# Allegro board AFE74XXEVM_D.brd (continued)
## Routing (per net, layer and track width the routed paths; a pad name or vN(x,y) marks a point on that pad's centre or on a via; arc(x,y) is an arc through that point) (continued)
N19409548: length 12.5
  TOP w0.127: U7.20 175.62,111.64 175.62,112.62 178.08,115.09 181.81,115.09 182.04,115.32 183.82,115.32 184.31,114.82 U5.26
N19409557: length 8.9
  TOP w0.127: v1(177.42,112.19) 177.42,111.47 177.19,111.24 177.19,111.09 176.82,110.72 U7.18
  BOTTOM w0.127: v3(183.81,113.37) 183.81,113.35 182.78,112.32 177.55,112.32 v1(177.42,112.19)
N19409566: length 9.4
  L4_SIG w0.127: v3(176.53,110.22) 177.94,110.22 178.08,110.08 182.14,110.08 182.83,110.77 182.83,112.89 v3(183.31,113.37)
N19409575: length 8.8
  L4_SIG w0.127: v3(176.53,109.72) 176.21,110.04 176.21,110.06 176.19,110.08 176.19,110.37 176.54,110.72 178.1,110.72 178.43,111.05 179.65,111.05 180.86,112.26 181.88,112.26 182.37,112.75 182.37,112.98 182.76,113.37 v3(182.81,113.37)
N19410556: length 11.7
  TOP w0.127: U5.30 v1(182.31,114.88)
  BOTTOM w0.127: v3(176.53,109.22) 176.56,109.22 177.24,109.91 177.24,111.66 176.83,112.06 176.83,112.5 179.22,114.88 v1(182.31,114.88)
N19410565: length 7.8
  TOP w0.127: U5.32 181.28,113.41 179.81,113.41 177.47,111.07 177.47,110.16 177.17,109.86 177.17,108.92 176.97,108.72 U7.14
N19410574: length 5.4
  TOP w0.127: U7.13 176.98,108.22 177.47,108.71 177.47,109.58 177.83,109.93 177.83,111.02 178.3,111.5 U5.33
N19410583: length 5.5
  TOP w0.127: U7.12 177.04,107.72 177.83,108.51 177.83,109.3 178.13,109.6 178.13,110.85 178.28,111 U5.34
N19439857: length 1.6
  BOTTOM w0.127: R33.1 151.05,114.6 J12.1
N19439882: length 1.6
  BOTTOM w0.127: J12.3 153.54,114.55 R32.1
N19439919: length 1.6
  BOTTOM w0.127: R35.1 156.11,114.58 J12.5
N19439930: length 1.6
  BOTTOM w0.127: R34.1 158.72,114.66 J12.7
N19439963: length 1.5
  BOTTOM w0.127: R36.1 161.42,114.81 J12.9
N19439974: length 1.6
  BOTTOM w0.127: J12.11 163.7,114.55 R37.1
N19440007: length 1.6
  BOTTOM w0.127: J12.13 166.24,114.55 R39.1
N19440018: length 1.6
  BOTTOM w0.127: J12.15 168.78,114.55 R38.1
N19452593:
  vias: v1(117.88,96.55)
N19452616: length 5.7
  TOP w0.127: R18.1 117.75,95.53 116.84,96.44 116.84,98.96 D1.2
N19452717:
  vias: v1(120.27,96.52)
N19452732: length 12.3
  TOP w0.127: D2.2 117.45,102.54 117.45,97.59 117.98,97.05 118.72,97.05 120.24,95.53 R19.1
N19463241:
  vias: v1(119.35,11.39)
N19466012: length 1.8
  TOP w0.305: U29.14 134.53,24.32 R279.1
N19467594: length 0.3
  BOTTOM w0.254: v1(61.55,62.3) 61.73,62.49 R20.1
N19500229: length 43.9
  BOTTOM w0.127: R26.2 123.6,93.7 Q3.3 Q4.3 Q5.3 Q6.3 Q7.3 Q8.3 Q9.3 Q10.3 Q11.3 Q12.3 Q13.3 Q14.3 Q15.3 Q16.3 Q17.3 Q18.3 Q19.3 Q20.3
N19509945: length 7.6
  TOP w0.127: D3.2 117.14,93.73 v1(122.56,93.73)
N19512252: length 6
  BOTTOM w0.127: v3(176.61,101.74) 177.56,101.74 179.07,103.25 179.07,105.65 179.42,106 v3(179.44,106)
N19512261: length 6.3
  BOTTOM w0.127: v3(176.61,101.24) 177.59,101.24 179.81,103.46 179.81,105.15 179.46,105.5 v3(179.44,105.5)
N19512270: length 6.8
  TOP w0.127: U9.12 177.22,100.74 177.72,101.24 177.72,104.62 178.1,105 U5.46
N19520191: length 11.8
  TOP w0.127: U5.55 184.31,97.17 183.26,96.11 181.79,96.11 180.23,94.55 U10.10
N19520200: length 11.8
  TOP w0.127: U5.57 185.31,99.85 184.68,99.22 184.68,96.93 183.49,95.73 182.14,95.73 180.88,94.47 U10.11
N19525330: length 11.8
  TOP w0.127: U5.59 186.31,100.78 186.09,100.55 186.09,99.33 185.88,99.11 185.88,96.85 183.97,94.95 182.5,94.95 182.18,94.63 U10.13
N19525339: length 11.8
  TOP w0.127: U10.12 181.53,94.51 182.35,95.33 183.69,95.33 185.04,96.67 185.04,97.71 185.03,97.72 185.03,98.07 185.04,98.08 185.04,99.01 185.81,99.78 U5.58
N19667706: length 2.2
  TOP w0.127: D14.1 211.96,89.81 R287.2
N19816997: length 2
  BOTTOM w0.381: C2.2 43.84,69.32 arc(43.67,69.2) 43.47,69.16 T1.4
N19898860: length 15.9
  TOP w0.127: J36.3 161.37,91.9 163.17,93.7 170.74,93.7 172.16,95.12 173.16,95.12 173.7,95.66 U33.13
N19898869: length 13.9
  TOP w0.127: J36.6 165.33,92.76 170.51,92.76 171.88,94.13 173.2,94.13 174.35,95.28 U33.12
N19898878: length 12
  TOP w0.127: U33.11 175,95.32 173.48,93.8 172.24,93.8 170.73,92.29 167.4,92.29 J36.9
N19898887: length 10.2
  TOP w0.127: J36.12 170.46,91.34 172.57,93.45 173.91,93.45 175.65,95.18 U33.10
N20069404: length 13.3
  TOP w0.305: v1(92.04,18.71) 91.61,18.71 91.42,18.53 Q25.D2
  L6_SIG w0.127: v3(91.3,8.44) 91.3,9.44 90.14,10.59 90.14,11.89 v1(89.18,12.85)
  BOTTOM w0.127: v1(89.18,12.85) 89.18,15.37 92.04,18.23 v1(92.04,18.71)
N20069410: length 14.9
  TOP w0.305: L45.1 95.43,8.31 93.92,8.95 93.66,8.95 95.35,8.97 L45.1 ; L45.1 97,9.19 95.25,9.19 93.85,8.99 ; L45.1 97,8.33 93.85,8.99 ; 93.85,8.99 U13.7
N20069434: length 2.2
  TOP w0.305: R233.2 R228.1 93.1,6.67 U13.5
N20069690: length 1.7
  TOP w0.305: 90.18,17.7 Q25.6 90.93,17.41 Q25.D1 ; 90.18,17.7 v1(90.17,17.7) ; 90.18,17.7 Q25.5
N20069712: length 2.1
  BOTTOM w0.305: R229.1 R232.1 v1(79.76,14.5)
N20069759:
  vias: v1(81.41,14.5)
N20070471: length 1.7
  TOP w0.305: 167.82,32.51 167.72,32.61 U32.1
  TOP w0.381: v1(170.18,31.8) 169.96,31.58 U32.20
  vias: v1(170.18,32.72) v1(171.15,32.72) v1(171.15,31.8) v1(172.11,32.74) v1(172.11,31.83)
N20070473:
  vias: v1(167.03,27.51)
N20070515: length 0.3
  BOTTOM w0.381: R298.2 165.74,27.71 v1(165.77,27.67)
N20070523: length 0.4
  TOP w0.381: U32.11 164.88,27.91 v1(164.8,27.91)
N20070610:
  vias: v1(163.81,28.98)
N20070750: length 0.1
  BOTTOM w0.381: v1(163.81,29.63) 163.8,29.64 R300.2
N20073169: length 14
  TOP w0.381: v3(165.71,13.96) v3(165.71,14.48) 165.71,15.54 ; 165.71,15.54 165.91,17.45 166.04,19 v1(165.58,19) L48.1 ; 165.71,15.54 165.71,16.23 ; 165.71,15.54 165.74,15.75 165.61,16.76 165.56,17.53 165.55,18.36 ; 165.71,16.23 165.55,18.36 ; 165.71,16.23 165.71,18.2 165.55,18.36
  vias: v1(165.63,18.34) v1(165.61,17.73) v3(165.71,13.46)
N20073179: length 14
  TOP w0.381: v1(165.77,8.05) 165.71,8.12 165.63,8.81 165.71,11.13 ; v1(165.77,8.05) 165.63,9.12 165.61,7.39 165.68,7.42 166.14,7.39 165.75,10.63 ; v1(165.77,8.05) 165.89,9.04 165.81,9.27 165.75,10.63 ; 165.71,11.13 v3(165.71,11.84) v3(165.71,12.36) ; 165.71,11.13 165.75,10.63
  vias: v1(165.79,8.71) v1(165.81,7.42) v3(165.71,12.88)
N20073199: length 2.7
  TOP w0.254: R247.2 v1(163.16,12.78)
  TOP w0.305: U18.14 163.96,13.16 163.59,12.78 R247.2 162.24,13.73 R248.1
N20073285:
  vias: v1(167.11,12.11)
N20073325:
  vias: v1(164.31,14.2)
N20074418:
  vias: v1(145.57,26.47)
N20074438: length 2.2
  TOP w0.203: 143.66,32.84 C406.1 143.66,30.77 C407.1
  vias: v1(143.71,29.97) v1(143.76,32.51) v1(143.76,31.09) v1(145.03,32.56) v1(145.01,31.37) v1(145.01,30.1) v1(145.92,32.56) v1(145.9,31.37) v1(145.9,30.12) v1(146.79,32.56) v1(146.76,31.37) v1(146.79,30.1)
N20074448: length 1.3
  TOP w0.381: v1(150.24,27.13) 150.26,27.11 U27.12 151.01,27.11 v1(151.03,27.13)
  BOTTOM w0.305: C412.1 v1(150.24,27.13)
N20074452: length 0.3
  BOTTOM w0.305: R276.2 146.58,25.23 v1(146.66,25.16)
N20074454: length 1.7
  TOP w0.305: U27.3 143.87,27.76 C408.1
N20074458: length 0.2
  BOTTOM w0.305: R278.2 147.42,25.27 v1(147.31,25.16)
N20074494: length 2.5
  TOP w0.254: R275.1 148.39,32.12 148.38,32.12 148.25,32.25 148.25,32.26 147.84,32.66 R274.1
  TOP w0.305: R274.1 147.73,33.6 PP25.1
N20074551: length 0.6
  BOTTOM w0.305: U28.1 148.7,32.66 v1(148.73,32.69)
N20074589: length 2
  TOP w0.305: C409.1 152.48,27.76 U27.13
N20074804: length 1.3
  TOP w0.381: v1(150.24,28.42) 150.25,28.41 U27.14 150.87,28.41 v1(150.88,28.42)
  BOTTOM w0.305: v1(150.88,28.42) R273.1 v1(150.24,28.42)
N20081535: length 0.4
  TOP w0.305: v1(80.98,22.91) 80.78,22.72 U22.6
N20081541: length 1.9
  TOP w0.305: C373.1 86.17,25.7 C452.1
  vias: v1(84.69,23.94) v1(85.32,25.55) v1(86,22.64) v1(86,21.99) v1(86.69,25.55) v1(87.86,25.58) v1(88.13,22.54) v1(88.16,23.34)
N20081551:
  vias: v1(82.73,19.08) v1(82.73,18.41)
N20081555:
  vias: v1(80.98,22)
N20081559: length 1.8
  TOP w0.305: C377.1 83.39,25.45 U22.3
N20081574:
  vias: v1(80.78,20.04)
N20081656: length 2.5
  TOP w0.305: R256.1 87.68,20.65 88.6,21.56 R255.1 PP16.1
N20081707: length 0.5
  BOTTOM w0.305: U21.1 88.55,20.64 v1(88.6,20.6)
N20081783: length 1.7
  TOP w0.305: C381.1 83.39,17.02 U22.13
N20082233:
  vias: v1(84.04,18.73)
N20086063: length 0.3
  BOTTOM w0.381: R270.2 126.67,5.21 v1(126.82,5.06)
N20086075: length 1.9
  TOP w0.305: v1(123.93,12.29) 123.8,12.17 C397.1 123.8,10.67 v1(123.98,10.49)
  vias: v1(123.95,11.4) v1(123.98,9.55) v1(126.01,12.52) v1(125.98,11.35) v1(125.96,10.29) v1(127.03,11.35) v1(127,10.29) v1(127.05,12.52)
N20086085: length 0.4
  BOTTOM w0.381: C401.1 130.74,7.04 v1(130.72,7.02)
N20086089: length 0.2
  BOTTOM w0.381: v1(127.47,5.06) 127.58,5.18 R271.2
N20086091: length 1.8
  TOP w0.305: U25.3 124,7.67 C399.1
N20086095:
  vias: v1(129.44,5.18)
N20086131: length 2.8
  TOP w0.254: R269.1 128.91,11.81 R268.1
  TOP w0.305: R268.1 127.97,13.92 PP23.1
N20086161: length 0.6
  BOTTOM w0.305: U26.1 128.92,12.68 v1(128.98,12.75)
N20086199: length 1.9
  TOP w0.305: U25.13 C400.1
N20086237:
  vias: v1(130.72,8.32)
N20090664: length 0.2
  BOTTOM w0.381: R261.1 121.74,24.36 v1(121.68,24.42)
N20090676: length 2.4
  TOP w0.203: 114.91,28.7 114.78,28.57 C386.1 114.78,26.6 C453.1
  vias: v1(114.94,28.5) v1(114.94,27.64) v1(114.94,26.64) v1(114.91,25.73) v1(116.41,28.65) v1(116.38,27.69) v1(116.41,26.72) v1(117.32,28.65) v1(117.37,27.71) v1(117.35,26.75) v1(118.19,28.65) v1(118.21,27.69) v1(118.21,26.75)
N20090711: length 0.3
  BOTTOM w0.381: v1(116.47,22.47) 116.57,22.38 R263.2
N20090727: length 0.4
  BOTTOM w0.381: C391.1 121.85,22.96 v1(121.68,23.12)
N20090731:
  vias: v1(117.78,21.17)
N20090737: length 1.8
  TOP w0.305: U23.3 114.88,23.77 C390.1
N20090741:
  vias: v1(119.76,21.08)
N20090777: length 2.7
  TOP w0.254: R262.1 120.03,27.74 R264.1
  TOP w0.305: R262.1 119.09,29.8 PP21.1
N20090807: length 0.5
  BOTTOM w0.305: v1(120.05,28.71) 120.08,28.68 U24.1
N20090845: length 1.8
  TOP w0.305: C392.1 123.44,23.77 U23.13
N20133985: length 3
  TOP w0.381: 43.34,33.08 43.58,33.97 arc(43.64,34.1) 43.76,34.2 44.21,34.46 arc(44.36,34.59) 44.45,34.78 T5.1
N20133989: length 3
  TOP w0.381: T5.3 41.98,35.37 arc(41.97,35.22) 42.02,35.07 42.31,34.57 arc(42.36,34.43) 42.35,34.28 T4.4
N20135778:
  vias: v1(43.62,36.54)
N20136307: length 3.2
  TOP w0.381: C141.1 59.25,39.84 arc(58.97,39.01) 59.03,38.14 T9.4
N20136325: length 1.8
  TOP w0.381: C141.2 59.06,40.97 L9.2 58.91,41.52 58.74,42.12 C142.2
N20136327: length 1.8
  TOP w0.381: C143.2 59.72,42.39 L9.1 60.05,41.15 C140.2
N20136329: length 1.8
  TOP w0.381: C143.1 59.49,43.34 L10.1 59.17,44.56 R77.2
N20136331: length 1.8
  TOP w0.381: C142.1 58.52,43.04 L10.2 58.19,44.2 R73.2
N20136361: length 3
  TOP w0.381: T9.1 62.8,33.87 arc(62.81,33.72) 62.76,33.58 62.47,33.07 arc(62.43,32.93) 62.44,32.79 T8.5
N20136363: length 3
  TOP w0.381: T8.4 61.21,32.44 arc(61.15,32.58) 61.03,32.68 60.53,32.97 arc(60.42,33.07) 60.35,33.2 T9.3
N20136391: length 0.7
  TOP w0.381: 58.13,45.12 C144.2
N20136393: length 0.7
  TOP w0.381: R77.1 C145.2
N20136405: length 2.7
  TOP w0.381: C137.1 L4.2 64.02,21.92 R74.2 64.26,21.08
N20136526: length 3.2
  TOP w0.381: T9.6 61.48,38.8 arc(61.1,39.58) 60.44,40.15 C140.1
N20136572:
  vias: v1(61.2,34.98)
N20138109: length 3.3
  TOP w0.381: C157.1 44.45,85.45 arc(43.88,85.95) 43.55,86.63 T13.6
N20138119: length 1.8
  TOP w0.381: 45.08,83.76 44.92,84.36 C157.2 ; 45.08,83.76 45.24,83.17 C159.2 ; 45.08,83.76 L13.2
N20138121: length 2.4
  TOP w0.381: 46.23,83.39 L13.1 ; 46.23,83.39 L13.1 ; 46.23,83.39 46.12,83.2 ; L13.1 45.89,84.66 C158.2
N20138123: length 1.8
  TOP w0.381: C160.1 46.5,82.48 L14.1 46.82,81.29 R97.2
N20138125: length 1.8
  TOP w0.381: C159.1 45.52,82.23 L14.2 45.86,80.97 R95.2
N20138185: length 0.7
  TOP w0.381: R95.1 C146.2
N20138187: length 0.7
  TOP w0.381: R97.1 C147.2
N20138199: length 2.7
  TOP w0.381: R94.2 R93.2 L11.2 C155.1
N20138318: length 3.3
  TOP w0.381: T13.4 45.95,87.46 arc(46.01,86.54) 45.71,85.66 C158.1 45.54,85.36
N20138362:
  vias: v1(43.8,90.59)
N20138813: length 3.3
  TOP w0.381: T17.6 59.35,88.5 arc(59.32,87.91) 59.51,87.35 C149.1
N20138823: length 1.9
  TOP w0.381: C149.2 59.79,86.15 59.47,86.02 L17.2 59.13,84.76 C151.2
N20138825: length 1.8
  TOP w0.381: 60.34,85.98 60.46,85.77 L17.1 60.14,84.58 C152.2
N20138827: length 1.7
  TOP w0.381: C152.1 59.84,83.52 59.69,82.99 59.56,82.5 R116.2
N20138829: length 1.7
  TOP w0.381: R114.2 58.57,82.8 L18.2 58.88,83.82 C151.1
N20138855: length 3
  TOP w0.381: T16.5 61.65,94.6 arc(61.58,94.47) 61.47,94.37 60.97,94.08 arc(60.85,93.98) 60.79,93.85 T17.1
N20138857: length 3
  TOP w0.381: T16.4 62.9,94.36 arc(62.88,94.09) 62.97,93.84 63.19,93.44 arc(63.24,93.3) 63.23,93.16 T17.3
N20138889: length 0.7
  TOP w0.381: C153.2 R114.1
N20138891: length 0.7
  TOP w0.381: C154.2 R116.1
N20138903: length 2.7
  TOP w0.381: R115.2 R119.2 L15.2 C148.1
N20139022: length 3.3
  TOP w0.381: T17.4 61.83,87.92 arc(61.53,87.32) 61.03,86.88 60.49,86.57 C150.1
N20148716: length 3
  TOP w0.381: T12.4 43.76,93.2 arc(43.82,93.06) 43.94,92.97 44.28,92.76 arc(44.52,92.55) 44.66,92.27 T13.3
N20186999: length 3
  TOP w0.381: T13.1 42.19,91.7 arc(42.17,91.92) 42.24,92.13 42.46,92.51 arc(42.53,92.71) 42.52,92.92 T12.5
N20188389:
  vias: v1(61.59,91.98)
N20203110: length 3.1
  TOP w0.203: 157.48,7.14 157.48,6.02 Q26.1 158.48,5.01 R329.2
N20221008: length 3.2
  TOP w0.381: T7.4 48.85,38.93 arc(49.22,39.68) 49.84,40.22 C469.1
N20221026: length 1.8
  TOP w0.127: L52.2 50.41,41.87
  TOP w0.381: C472.2 50.57,42.47 50.25,41.28 50.39,41.04
N20221028: length 1.8
  TOP w0.381: C470.2 51.22,40.98 L52.1 51.56,42.24 C473.2
N20221030: length 1.8
  TOP w0.381: 52.03,44.59 52.16,44.37 L53.1 51.83,43.15 C473.1
N20221032: length 1.8
  TOP w0.381: R333.2 51.13,44.58 L53.2 50.85,43.41 C472.1
N20221062: length 3
  TOP w0.381: T7.1 49.97,33.3 arc(49.88,33.12) 49.73,32.98 49.28,32.72 arc(49.16,32.62) 49.1,32.49 T6.5
N20221064: length 3
  TOP w0.381: T6.4 47.87,32.8 arc(47.88,32.95) 47.83,33.09 47.54,33.59 arc(47.49,33.74) 47.5,33.89 T7.3
N20221092: length 0.7
  TOP w0.381: 51.72,45.99 51.55,45.35
N20221094: length 0.7
  TOP w0.381: C475.2 R334.1
N20221106: length 2.7
  TOP w0.381: R332.2 R331.2 45.08,22.37 L50.2 45.54,24.11
N20221227: length 3.2
  TOP w0.381: C470.1 50.87,40.28 51.14,39.82 arc(51.38,39.1) 51.33,38.35 T7.6
N20221265:
  vias: v1(49.14,35.09)
N20221700: length 3
  TOP w0.381: T10.5 67.96,34.26 arc(67.95,34.41) 67.99,34.55 68.17,34.81 arc(68.3,35.12) 68.29,35.45 T11.1
N20221704: length 3.3
  TOP w0.381: C477.1 64.97,41.52 64.77,41.32 arc(64.49,40.49) 64.55,39.62 T11.4
N20221714: length 1.8
  TOP w0.381: C477.2 64.57,42.44 L56.2 64.26,43.6 C480.2
N20221716: length 1.8
  TOP w0.381: C478.2 65.57,42.63 L56.1 65.24,43.87 C481.2
N20221718: length 1.8
  TOP w0.381: C481.1 65.01,44.82 L57.1 64.69,46.04 R339.2
N20221720: length 1.8
  TOP w0.381: R338.2 63.71,45.84 63.9,45.14 ; 63.9,45.14 L57.2 ; 63.9,45.14 64.07,44.51 C480.1
N20221748: length 3
  TOP w0.381: T11.3 65.87,34.68 arc(65.94,34.54) 66.05,34.45 66.55,34.16 arc(66.67,34.06) 66.73,33.92 T10.4
N20221780: length 0.7
  TOP w0.381: R338.1 C482.2
N20221782: length 0.7
  TOP w0.381: 64.12,47.4 64.29,46.77
N20221794: length 2.7
  TOP w0.381: R337.2 R336.2 L54.2 C479.1
N20221915: length 3.2
  TOP w0.381: C478.1 65.96,41.63 arc(66.62,41.06) 67,40.28 67.17,39.64 T11.6
N20221947:
  vias: v1(66.73,36.48)
N20222985: length 3
  TOP w0.381: T14.5 48.05,94.37 arc(48.06,94.17) 47.98,93.97 47.83,93.76 arc(47.7,93.46) 47.72,93.12 47.92,92.38 T15.1
N20222995: length 3
  TOP w0.381: T14.4 49.26,94.79 arc(49.41,94.51) 49.66,94.31 49.81,94.23 arc(50.02,94.07) 50.14,93.84 T15.3
N20223001: length 3.3
  TOP w0.381: T15.6 49.07,88.11 arc(49.4,87.43) 49.97,86.93 C485.1
N20223005: length 1.8
  TOP w0.381: C485.2 50.47,85.78 L60.2 50.76,84.65 C488.2
N20223007: length 1.8
  TOP w0.381: C489.2 51.75,84.87 51.58,85.45 ; L60.1 51.58,85.45 ; 51.58,85.45 51.41,86.14 C486.2
N20223009: length 1.8
  TOP w0.381: R344.2 52.34,82.77 L61.1 52.02,83.96 C489.1
N20223011: length 1.8
  TOP w0.381: R343.2 51.38,82.45 L61.2 51.04,83.71 C488.1
N20223065: length 0.7
  TOP w0.381: R343.1 C490.2
N20223067: length 0.7
  TOP w0.381: C491.2 R344.1
N20223080: length 3.6
  TOP w0.381: L58.2 R341.2 ; L58.2 C487.1 ; L58.2 R341.2 ; R341.2 R342.2
N20223194: length 3.3
  TOP w0.381: C486.1 51.23,87.14 arc(51.53,88.01) 51.47,88.94 T15.4
N20223236:
  vias: v1(49.32,92.07)
N20223673: length 3
  TOP w0.381: T19.1 66.31,92.37 arc(66.37,92.5) 66.49,92.6 66.99,92.89 arc(67.1,92.99) 67.17,93.12 T18.5
N20223681:
  vias: v1(67.11,90.48)
N20223685: length 3.3
  TOP w0.381: T19.6 64.87,87.02 arc(64.84,86.43) 65.03,85.87 C493.1
N20223687: length 1.7
  TOP w0.381: C496.2 64.67,83.41 L64.2 64.97,84.45 C493.2
N20223689: length 1.8
  TOP w0.381: C494.2 65.98,84.29 L64.1 65.66,83.1 C497.2
N20223691: length 1.7
  TOP w0.381: C497.1 65.35,82.02 L65.1 65.05,81 R349.2
N20223693: length 1.7
  TOP w0.381: R348.2 64.06,81.28 L65.2 64.39,82.35 C496.1
N20223728: length 3
  TOP w0.381: 68.52,90.8 68.75,91.68 arc(68.76,91.82) 68.71,91.97 68.49,92.36 arc(68.4,92.61) 68.42,92.88 T18.4
N20223751: length 0.7
  TOP w0.381: 63.87,79.72 R348.1
N20223753: length 0.7
  TOP w0.381: C498.2 R349.1
N20223766: length 3.5
  TOP w0.381: L62.2 C495.1 L62.2 ; L62.2 R346.2 R347.2
N20223882: length 3.3
  TOP w0.381: 66.01,85.09 66.55,85.4 arc(67.05,85.84) 67.35,86.44 T19.4
N20382523: length 4.8
  TOP w0.305: JP9.2 166.42,22.97 U32.13
N176074941: length 0.6
  TOP w0.254: C225.2 R160.1
N176076570: length 0.7
  TOP w0.381: C222.2 97.84,93.54 R153.1
N188647412: length 0.9
  TOP w0.305: R207.2 Q23.3
N188648232: length 0.9
  TOP w0.305: R201.2 Q21.3

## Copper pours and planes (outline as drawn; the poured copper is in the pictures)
1.8V_USB on L3_PWR: 172.72,90.17 172.72,92.71 173.61,92.71 173.61,99.57 172.97,100.2 172.97,111.63 175.51,111.63 176.4,110.74 177.04,110.74 177.67,111.38 177.67,120.4 182.37,120.4 182.37,115.7 181.23,114.55 181.23,112.01 182.75,110.49 192.41,110.49 192.41,101.09 188.34,101.09 188.34,104.77 185.55,107.57 177.93,107.57 175.9,105.54 175.9,104.14 176.28,103.76 180.47,103.76 181.48,102.74 181.48,99.57 183.52,99.57 183.52,97.66 179.2,97.66 179.2,90.17
3.3V_USB on TOP: 196.96,96.99 196.96,99.28 194.24,99.28 194.24,96.99
3.3V_USB on L3_PWR: 167.44,85.72 167.44,123.19 197.15,123.19 197.15,96.52 188.77,96.52 188.77,85.72
5.0V_SOURCE on BOTTOM (solid shape): 188.62,8.98 184.1,8.98 184.1,12.79 188.62,12.79
5.0V_SOURCE on TOP, BOTTOM: 184.02,1.52 184.02,12.7 188.72,12.7 188.98,12.95 188.98,16.51 188.21,17.27 185.93,17.27 185.93,20.07 195.45,20.07 195.45,1.52
12VFMC on L6_SIG: 212.09,41.91 212.09,45.72 214.63,45.72 214.63,41.91
+1.0V_ANALOG_SENSE on TOP: 108.2,4.95 108.2,16.54 110.87,19.2 110.87,22.35 109.6,23.62 106.63,23.62 103.58,20.57 98.55,20.57 98.55,22.86 102.54,22.86 106.32,26.64 108.43,26.64 108.86,27.08 108.86,30.48 111.23,30.48 111.23,25.98 113.11,24.1 113.11,19.28 113.46,18.92 114.94,18.92 115.82,18.03 115.82,16.51 111.89,16.51 110.62,15.24 110.62,4.95
+1.0V_SENSE on TOP: 142.34,33.32 147.19,33.32 147.19,35 141.17,35 139.22,33.05 132.56,33.05 132.54,33.02 132.54,31.52 140.54,31.52
+1.0V_SENSE on BOTTOM: 147.19,35.03 147.19,33.35 144.86,33.35 144.86,35.03
+1.2V_RX_PWR_SENSE on TOP: 113.79,31.12 113.79,29.62 118.39,29.62 118.39,31.12
+1.2V_RX_PWR_SENSE on BOTTOM: 118.41,31.17 118.41,29.62 115.85,29.62 115.85,31.17
+1.5V_SENSE on TOP: 123.6,31.65 123.6,30.12 126.67,30.12 127.28,29.51 129.44,29.51 129.44,31.65
+1.5V_SENSE on BOTTOM: 129.54,31.14 129.54,29.39 127.28,29.39 127.28,31.14
+1.8V_ANALOG_SENSE on TOP: 89.53,22.28 89.53,27.36 77.75,27.36 77.75,29.06 97.61,29.06 97.61,27.36 91.49,27.36 91.49,22.28
+1.8V_ANALOG_SENSE on BOTTOM: 89.64,23.6 89.64,22.33 90.98,22.33 91.24,22.58 91.24,23.6
+1.8V_RX_PWR_SENSE on TOP: 122.61,15.06 122.61,13.46 127.33,13.46 127.33,15.06
+1.8V_RX_PWR_SENSE on BOTTOM: 127.33,15.06 127.33,13.46 125.04,13.46 125.04,15.06
+2.2V on TOP: 130.88,24.69 130.88,26.7 132.12,26.7 132.12,28.45 133.32,28.45 133.32,26.7 133.59,26.7 133.59,24.69
+2.2V on TOP: 128.57,8.77 128.57,10.77 129.81,10.77 129.81,12.53 131,12.53 131,10.77 131.28,10.77 131.28,8.77
+2.2V on TOP: 148.41,28.88 148.41,30.89 149.66,30.89 149.66,32.64 150.85,32.64 150.85,30.89 151.13,30.89 151.13,28.88
+2.2V on TOP: 158.62,8.28 158.62,18.39 159.92,19.69 164.59,19.69 164.59,17.53 161.42,17.53 160.71,16.81 160.71,13.94 161.49,13.16 162.47,13.16 162.47,12.17 161.5,12.17 160.76,11.43 160.76,9.42 161.29,8.89 164.72,8.89 164.72,6.86 160.05,6.86
+2.2V on TOP: 119.63,24.97 119.63,26.97 120.62,26.97 120.62,28.73 121.82,28.73 121.82,26.97 122.4,26.39 122.4,24.97
+2.2V on TOP: 117.32,11.89 117.32,13.89 118.57,13.89 118.57,15.65 119.76,15.65 119.76,13.89 120.04,13.89 120.04,11.89
+2.2V on TOP: 84.43,20.75 86.44,20.75 86.44,19.85 88.19,19.85 88.19,18.39 86.44,18.39 86.44,18.37 84.43,18.37
+2.2V on BOTTOM: 132.07,28.45 132.07,25.08 132.44,24.72 133.6,24.72 133.6,28.45
+2.2V on BOTTOM: 149.61,32.64 149.61,28.91 151.21,28.91 151.21,32.64
+2.2V on BOTTOM: 88.29,19.69 85.72,19.69 85.57,19.53 85.57,18.3 88.29,18.3
+2.2V on BOTTOM: 120.57,28.73 120.57,26.19 120.7,26.06 122.28,26.06 122.28,28.73
+2.2V on BOTTOM: 129.84,12.53 129.84,9.78 131.32,9.78 131.32,12.53
+2.2V on BOTTOM: 118.54,15.65 118.54,12.95 120.04,12.95 120.04,15.65
+2.2V on BOTTOM: 158.62,8.28 158.62,18.39 159.92,19.69 164.59,19.69 164.59,17.53 161.16,17.53 160.71,17.07 160.71,14.68 161.37,14.02 162.43,14.02 162.43,12.57 161.01,12.57 160.4,11.96 160.4,9.78 161.29,8.89 164.72,8.89 164.72,6.86 160.05,6.86
+2.2V on L6_SIG: 105.03,7.11 96.27,15.88 85.6,15.88 85.6,19.94 112.14,19.94 116.33,15.75 119.76,15.75 122.17,13.34 138.81,13.34 140.84,11.3 142.24,11.3 146.43,15.49 137.29,24.64 120.52,24.64 120.52,29.21 144.15,29.21 147.45,32.51 158.12,32.51 158.12,19.63 163.98,19.63 164.64,18.97 164.64,7.11 ; 2 cut-outs
+2.5VCLK on TOP: 165.66,37.34 165.66,32.36 167.06,32.36 167.06,37.34
+2.5VCLK on BOTTOM: 165.61,33.73 165.61,37.34 167.08,37.34 167.08,33.73
+2.5VCLK on L3_PWR: 117.47,73.02 83.82,73.02 82.55,74.3 82.55,109.86 95.89,109.86 95.89,103.5 91.44,99.06 91.44,81.91 92.08,81.28 123.83,81.28 167.64,37.46 167.64,33.71 156.79,33.71
+3.3VCLK on TOP: 96.32,95.55 96.32,96.95 97.66,96.95 97.66,95.55
+3.3VCLK on TOP: 102.31,99.97 102.31,101.73 106.93,101.73 106.93,100.25 105.11,100.25 104.83,99.97
+3.3VCLK on TOP: 95.19,85.32 96.23,86.35 97.3,85.27 96.27,84.24
+3.3VCLK on TOP: 176.68,36.88 176.68,32 178.49,32 178.49,36.88
+3.3VCLK on BOTTOM: 178.21,36.88 178.21,33.38 176.81,33.38 176.81,36.88
+3.3VCLK on L3_PWR: 168.91,33.35 168.91,39.37 126.37,81.91 93.34,81.91 92.08,83.19 92.08,97.79 97.16,102.87 97.16,109.86 100.97,113.66 107.95,113.66 114.02,107.59 114.02,95.53 115.04,94.51 139.8,94.51 178.71,55.6 178.71,33.35
+5VIN on TOP: 170.31,29.18 170.31,21.34 167.44,21.34 167.44,28.02 168.61,29.18
+5VIN on TOP: 181.25,28.96 181.25,24.28 177.93,24.28 177.93,28.96
+5VIN on TOP: 194.67,91.48 194.67,94.36 193.73,95.29 190.48,95.29 189.82,94.63 189.82,91.48
+5VIN on TOP: 166.19,15.57 166.5,15.88 166.5,17.2 187.35,17.2 187.35,13.18 170.54,13.18 170.54,2.79 166.19,2.79 164.9,4.09 159.99,4.09 159.77,4.32 159.77,5.71 160.1,6.05 165.3,6.05 166.19,6.93
+5VIN on TOP: 89.56,20.9 89.56,18.39 90.58,18.39 90.58,19.33 91.14,19.89 91.14,20.9
+5VIN on TOP: 88.65,6.53 88.65,9.22 90.07,9.22 90.07,9.12 91.54,9.12 91.54,8.28 90.07,8.28 90.07,6.53
+5VIN on TOP, BOTTOM: 190.5,38.73 190.5,36.83 202.56,36.83 202.56,38.73
+5VIN on BOTTOM: 181.25,25.88 181.25,24.28 179.91,24.28 179.91,25.88
+5VIN on BOTTOM: 169.47,26.29 169.47,24.69 168.12,24.69 168.12,26.29
+5VIN on BOTTOM: 166.07,15.44 167.82,17.2 187.35,17.2 187.35,13.18 170.18,13.18 170.18,2.79 166.07,2.79
+5VIN on L3_PWR: 189.87,95.25 189.87,48.89 182.25,41.27 182.25,31.75 177.17,26.67 167.97,26.67 167.97,18.41 180.98,18.41 189.74,27.18 189.74,35.43 196.85,42.54 196.85,95.25
+5VIN on L6_SIG: 79.12,1.27 79.12,36.83 189.23,36.83 189.23,39.37 203.2,39.37 203.2,31.12 197.49,31.12 197.49,1.27
-1.8V on TOP: 82.45,12.83 82.45,10.19 89.76,10.19 90.6,9.35 90.6,6.35 92.96,6.35 92.96,10.29 91.95,11.3 91.95,15.14 89.92,15.14 89.92,12.83
-1.8V on BOTTOM: 82.45,12.83 82.45,11.68 85.27,11.68 86.94,10.01 89.94,10.01 90.6,9.35 90.6,6.35 92.96,6.35 92.96,10.29 91.95,11.3 91.95,15.14 89.92,15.14 89.92,12.83
DVDD on TOP, BOTTOM: 146.96,23.62 140.39,23.62 140.39,21.95 146.96,21.95
DVDD on L3_PWR: 135.33,21.72 135.33,36.12 109.22,62.23 66.83,62.23 66.07,61.47 55.09,61.47 55.09,66.55 55.25,66.55 56.13,65.66 61.72,65.66 62.05,65.97 63.58,70.97 63.58,72.72 78.41,72.72 80.65,70.48 115.57,70.48 147.07,38.99 147.07,21.72
GND on BOTTOM (solid shape): 24.51,63.44 25.6,63.44 25.6,63.08 24.51,63.08 24.51,62.37 23.05,62.37 23.05,62.73 24.1,62.73 24.1,63.79 23.05,63.79 23.05,64.15 24.51,64.15
GND on BOTTOM (solid shape): 35.92,62.51 37.01,62.51 37.01,62.15 35.92,62.15 35.92,61.44 34.46,61.44 34.46,61.8 35.51,61.8 35.51,62.86 34.46,62.86 34.46,63.22 35.92,63.22
GND on L4_SIG (solid shape): 152.41,39.94 152.51,39.88 152.49,39.77 152.33,39.61 105.78,39.61 105.69,39.67 105.71,39.79 105.87,39.94
GND on L4_SIG (solid shape): 168.33,69.45 168.35,69.34 168.26,69.28 167.06,69.28 164.51,71.82 164.49,71.93 164.58,72 165.79,72
GND on L4_SIG (solid shape): 202.24,72.55 202.26,72.44 202.17,72.38 201.9,72.38 198.52,75.76 198.5,75.87 198.59,75.93 198.86,75.93
GND on L4_SIG (solid shape): 173.74,72.6 173.76,72.49 173.67,72.43 173.03,72.43 170.41,75.04 170.41,75.58 170.05,75.94 170.03,76.05 170.12,76.11 170.23,76.11
GND on L4_SIG (solid shape): 198.21,74.21 198.23,74.1 198.14,74.04 185.16,74.04 185.15,74.03 180.21,74.03 180.11,74.09 180.13,74.2 180.43,74.5 197.93,74.5
GND on L4_SIG (solid shape): 161.13,75.26 161.15,75.15 161.06,75.08 156.91,75.08 154.95,73.13 101.13,73.13 100.56,73.7 100.53,73.81 100.63,73.88 105.08,73.88 106.72,75.51 160.87,75.51
GND on L4_SIG (solid shape): 64.82,78.29 64.92,78.23 64.9,78.12 63.44,76.67 63.44,76.54 61.52,74.61 61.52,74.32 61.3,74.1 60.86,74.1 60.77,74.16 60.79,74.27 61.04,74.52 61.04,74.93 64.4,78.29
GND on L4_SIG (solid shape): 169.67,75.27 169.67,74.74 172.72,71.69 197.48,71.69 198.63,70.54 198.65,70.43 198.56,70.37 172.47,70.37 172.07,70.76 172.07,71.06 167.92,75.22 167.92,75.39 167.76,75.56 167.74,75.67 167.83,75.73 169.21,75.73
GND on L4_SIG (solid shape): 66.92,82.21 67.01,82.14 66.99,82.03 66.64,81.68 66.08,81.68 59.73,75.33 59.73,75.17 59.68,75.13 59.24,75.13 57.91,73.79 57.91,73.12 58.08,72.95 58.08,72.4 57.87,72.19 57.76,72.17 57.7,72.26 57.7,73.8 59.28,75.37 59.28,76.11 62.6,79.44 63.58,79.44 66.35,82.21
GND on L4_SIG (solid shape): 203.02,73.98 203.02,73.96 203.5,73.48 203.52,73.48 203.56,73.44 203.59,73.36 203.56,73.29 203.48,73.17 203.45,73.03 203.42,72.95 203.35,72.92 203.34,72.91 202.92,72.91 199.51,76.32 199.49,76.43 199.59,76.49 200.51,76.49
GND on L4_SIG (solid shape): 61.77,47.18 64.78,47.18 64.93,47.33 64.99,47.33 65.33,46.99 67.48,46.99 70.09,44.37 70.12,44.37 79.12,35.38 81.35,35.38 81.39,35.42 81.45,35.42 81.49,35.38 84.07,35.38 84.08,35.38 86.68,35.38 86.68,35.38 102.34,35.38 102.79,35.82 102.9,35.84 102.96,35.75 102.96,35.45 102.49,34.99 78.58,34.99 72.04,41.53 72.04,41.73 69.99,43.78 69.99,43.98 69.48,44.49 69.28,44.49 67.04,46.73 61.33,46.73 60.92,47.14 60.92,47.73 59.07,49.58 59.04,49.58 58.51,50.11 58.49,50.22 58.59,50.29 58.66,50.29
GND on L4_SIG (solid shape): 68.29,63.72 68.38,63.67 68.38,63.57 68.71,63.07 69.03,63.57 69.04,63.67 69.12,63.72 71.68,63.72 74.98,60.41 75.01,60.3 74.91,60.24 72.9,60.24 70.47,62.66 67.24,62.66 67.15,62.71 67.14,62.8 67.16,62.89 67.14,62.98 67.16,63.07 67.24,63.11 67.62,63.11 68.22,63.72
GND on L4_SIG (solid shape): outline of 662 points within 54.24,59.56 55.98,67.18
GND on L4_SIG (solid shape): outline of 773 points within 56.69,61.21 61.43,65.79
GND on TOP: 172.39,29.18 172.39,31.01 169.93,31.01 169.93,29.18
GND on TOP: 181.61,26.04 181.61,24.23 183.13,24.23 183.13,26.04
GND on TOP: 169.95,26.34 169.95,24.64 171.3,24.64 171.3,26.34
GND on TOP: 184.3,29.49 184.3,31.47 181.86,31.47 181.86,29.49
GND on TOP: 178.71,33.6 178.71,36.45 180.09,36.45 180.09,33.6
GND on TOP: 167.61,33.81 167.61,36.68 168.99,36.68 168.99,33.81
GND on TOP, L2_GND, L3_PWR, L6_SIG, L8_PWR_SIG: 46.36,0.63 17.78,17.14 17.15,17.78 0.64,46.08 0.64,80.64 17.15,109.22 46.11,126.36 199.39,126.36 199.39,98.42 219.08,98.42 219.08,29.21 199.39,29.21 199.39,0.63 ; 2 cut-outs
GND on BOTTOM: 46.36,0.63 17.78,17.14 17.15,17.78 0.64,46.08 0.64,80.64 17.15,109.22 46.11,126.36 199.39,126.36 199.39,98.42 219.08,98.42 219.08,29.21 199.39,29.21 199.39,0.63 ; 4 cut-outs
GND on L5_GND, L7_GND, L9_GND: 46.36,0.63 17.78,17.14 17.15,17.78 0.64,46.08 0.64,80.64 17.15,109.22 46.11,126.36 199.39,126.36 199.39,98.42 219.08,98.42 219.08,29.21 199.39,29.21 199.39,0.63 ; 2 cut-outs
VDDA_1.0V on TOP, BOTTOM: 104.39,13.59 104.39,17.27 106.17,17.27 106.17,13.59
VDDA_1.0V on BOTTOM: 52.71,60.17 52.71,46.35 53.65,45.41 56.03,45.41 56.46,45.83 56.46,48.44 55.12,49.78 55.12,58.93 53.87,60.17
VDDA_1.0V on L4_SIG: 52.12,67.56 52.12,59.44 54.11,59.44 54.11,67.56
VDDA_1.0V on L8_PWR_SIG: 102.24,13.34 102.24,30.61 99.01,33.83 65.28,33.83 53.72,45.39 53.72,48.69 56.72,48.69 66.93,38.48 100.58,38.48 106.17,32.89 106.17,13.34
VDDA_1.8V on TOP, BOTTOM: 86.03,32.82 86.03,31.17 89.71,31.17 89.71,32.82
VDDA_1.8V on L3_PWR: 81.81,21.11 58.9,21.11 30.48,49.53 30.48,75.56 35.56,80.64 40.94,80.64 42.75,78.84 42.75,71.73 47.17,67.31 50.55,67.31 51.31,66.55 51.31,65.28 50.8,64.77 42.55,64.77 40.36,62.59 40.36,50.42 63.2,27.58 79.91,27.58 85.34,33.02 89.53,33.02 89.53,28.83
VDDA_1.8V on L4_SIG: 49.76,66.98 49.76,60.11 51.77,60.11 51.77,66.98
VDDA_SERDES_1.0V on TOP, BOTTOM: 136.3,36.75 136.3,35.28 139.93,35.28 139.93,36.75
VDDA_SERDES_1.0V on L8_PWR_SIG: 136.27,34.85 136.27,47.24 115.57,67.94 64.08,67.94 63.93,68.1 61.11,68.1 58.95,65.94 58.95,60.81 61.09,58.67 63.07,58.67 63.37,58.37 63.37,57 59.82,57 57.02,59.79 57.02,68.45 60.66,72.09 69.55,72.09 73.15,75.69 114.81,75.69 141.1,49.4 141.1,34.85
VDDCLK_1.0V on TOP, BOTTOM: 104.39,8.89 104.39,12.57 106.05,12.57 106.05,8.89
VDDCLK_1.0V on L3_PWR: 95.76,13.11 95.76,38.23 93.6,40.39 65.66,40.39 52.55,53.49 52.55,58.42 51.51,59.46 51.51,66.78 53.24,66.78 53.24,60.55 54.81,58.98 54.81,55.68 65.66,44.83 98.04,44.83 101.6,41.27 101.6,16.51 103.25,14.86 106.43,14.86 106.43,8.89 99.97,8.89
VDDE on TOP: 133.38,12.42 133.38,16.08 135,16.08 135,12.42
VDDE on BOTTOM: 133.38,12.45 133.38,16.1 135,16.1 135,12.45
VDDE on L8_PWR_SIG: 65.91,46.61 54.25,58.27 54.25,67.56 56.39,67.56 56.39,59.72 59.72,56.39 62.94,56.39 67.64,51.69 108.71,51.69 120.93,39.47 120.93,30.68 135.25,16.36 135.25,11.43 126.77,11.43 112.27,25.93 112.27,36.96 102.62,46.61
VDDGPIO_1.8V on TOP, BOTTOM: 90.2,32.82 90.2,31.17 93.93,31.17 93.93,32.82
VDDGPIO_1.8V on L3_PWR: 90.17,31.12 90.17,33.66 89.61,34.21 64.29,34.21 49.02,49.48 49.02,57.15 50.39,58.52 51.87,58.52 51.99,58.39 51.99,52.78 65.38,39.4 93.32,39.4 94.74,37.97 94.74,31.12
VDDL1_1.0V on TOP: 106.78,19.53 106.78,22.99 108.56,22.99 108.56,19.56 108.31,19.3 107.01,19.3
VDDL1_1.0V on BOTTOM: 106.78,19.3 106.78,22.99 108.56,22.99 108.56,19.3
VDDL1_1.0V on L8_PWR_SIG: 66.09,40.59 52.2,54.48 52.2,59.18 52.48,59.46 52.48,61.29 53.09,61.9 53.09,66.67 54,66.67 54,57.12 65.56,45.57 101.75,45.57 111.12,36.2 111.12,18.41 106.81,18.41 106.81,33.53 99.75,40.59
VDDL2_1.0V on TOP, BOTTOM: 104.14,4.06 104.14,7.75 105.92,7.75 105.92,4.06
VDDL2_1.0V on BOTTOM: 52.2,66.8 52.2,65.02 51.33,65.02 50.9,64.59 50.9,62.56 51.61,61.85 52.2,61.85 52.2,60.07 49.61,60.07 48.59,61.09 48.59,65.74 49.66,66.8
VDDL2_1.0V on L8_PWR_SIG: 50.62,3.81 17.53,36.9 17.53,66.2 26.95,75.62 47.35,75.62 52.07,70.89 52.07,68.07 52.44,67.7 52.44,65.67 52.04,65.28 51.87,65.28 51.71,65.43 51.49,66.24 51.49,66.45 48.59,69.55 29.74,69.55 24.33,64.13 24.33,39.17 53.42,10.08 113.66,10.08 113.66,3.81
VDDPLL_1.0V on TOP, BOTTOM: 94.49,20.32 94.49,24 96.27,24 96.27,20.32
VDDPLL_1.0V on L8_PWR_SIG: 57.95,17.65 31.73,43.87 31.73,58.81 38.61,65.68 48.87,65.68 51.38,63.17 51.38,63.02 51.21,62.84 50.65,62.58 42.55,62.62 38.1,58.17 38.1,46.35 60.07,24.38 95.76,24.38 96.27,23.88 96.27,19.81 94.11,17.65
VDDPLL_1.8V on TOP, BOTTOM: 77.39,32.82 77.39,31.17 81.08,31.17 81.08,32.82
VDDPLL_1.8V on L3_PWR: 81.15,29.59 81.15,32.79 64.26,32.79 44.45,52.6 44.45,59.82 46.23,61.59 50.17,61.59 51.31,62.74 51.31,64.01 51.05,64.26 43.15,64.26 40.97,62.08 40.97,50.44 62.71,28.7 80.26,28.7
VDDR_SERDES_1.5V on TOP, BOTTOM: 122.63,35.56 122.63,33.83 126.34,33.83 126.34,35.56
VDDR_SERDES_1.5V on L8_PWR_SIG: 69.09,53.24 63.27,59.05 61.59,59.05 59.49,61.16 59.49,65.71 61.42,67.64 63.37,67.64 63.37,65.86 62.05,65.86 61.59,65.41 61.59,61.59 62.15,61.04 67.64,61.04 68.81,59.87 110.57,59.87 128.4,42.04 128.4,33.55 122.56,33.55 122.56,39.62 108.94,53.24
VDDT_SERDES_1.0V on TOP: 131.32,36.8 131.32,35.23 135.08,35.23 135.08,36.8
VDDT_SERDES_1.0V on BOTTOM: 131.22,36.78 131.22,35.23 135.08,35.23 135.08,36.78
VDDT_SERDES_1.0V on L8_PWR_SIG: 129.67,34.87 129.67,44.96 114.33,60.3 72.75,60.3 71.7,61.34 62.23,61.34 62.1,61.47 62.1,65.53 62.23,65.66 66.19,65.66 67.38,66.85 115.4,66.85 135.13,47.12 135.13,34.87
VDDTX_1.0V on TOP, BOTTOM: 105.03,27.94 105.03,31.75 106.68,31.75 106.68,27.94
VDDTX_1.0V on L3_PWR: 102.41,27.94 102.41,41.86 98.65,45.62 65.48,45.62 55.17,55.93 55.17,59.13 53.37,60.93 53.37,64.39 54.81,64.39 54.81,61.8 56.74,59.87 56.74,58.19 65.23,49.71 101.42,49.71 106.68,44.45 106.68,27.94
VDDTX_1.8V on TOP, BOTTOM: 81.84,32.82 81.84,31.17 85.39,31.17 85.39,32.82
VDDTX_1.8V on L8_PWR_SIG: 58.67,27.18 38.79,47.06 38.79,57.84 42.98,62.03 50.7,62.03 51.79,63.12 51.79,63.47 51.89,63.58 52.73,63.58 52.96,63.35 52.96,62.81 48.76,58.61 46.07,58.61 44.45,57 44.45,50.16 61.85,32.77 85.72,32.77 85.72,27.18
VDDVCO_1.8V on TOP, BOTTOM: 94.79,32.82 94.79,31.17 98.48,31.17 98.48,32.82
VDDVCO_1.8V on L8_PWR_SIG: 54.06,11.15 25.01,40.21 25.01,63.21 30.6,68.81 48.26,68.81 52.2,64.87 52.2,63.86 52.04,63.7 51.51,63.7 49.17,66.04 37.47,66.04 31.05,59.63 31.05,43.24 57.58,16.71 94.31,16.71 96.77,19.18 96.77,25.53 95.89,26.42 94.62,26.42 94.36,26.67 94.36,32.89 98.04,32.89 101.35,29.59 101.35,16.89 95.61,11.15
VEE on TOP: 79.15,6.63 79.15,5.05 83.13,5.05 83.13,6.63
VEE on BOTTOM: 46.08,59.89 46.08,66.22 49.15,69.29 52.25,69.29 52.25,67.44 49.71,67.44 48.18,65.91 48.18,60.91 49.5,59.59 52.2,59.59 52.2,57.05 48.92,57.05
VEE on BOTTOM: 79.15,6.65 79.15,5.03 83.24,5.03 83.24,6.65
VEE on L3_PWR: 59.69,4.45 19.05,45.08 19.05,80.01 29.21,90.17 45.72,90.17 52.71,83.19 52.71,68.58 52.5,68.38 52.5,67.69 48.77,67.69 48.77,67.87 44.48,72.16 44.48,78.08 40.01,82.55 34.93,82.55 28.58,76.2 28.58,48.89 64.14,13.34 83.44,13.34 83.44,4.45
(no net) on L4_SIG: 46.36,0.63 17.78,17.14 17.15,17.78 0.64,46.08 0.64,80.64 17.15,109.22 46.11,126.36 199.39,126.36 199.39,98.42 219.08,98.42 219.08,29.21 199.39,29.21 199.39,0.63 ; 2 cut-outs
3P3V_FMC on L6_SIG: 210.19,44.45 210.19,37.46 213.36,37.46 213.36,44.45
3P3VAUX on L3_PWR: 186.69,19.69 186.69,22.23 191.14,26.67 191.14,34.92 205.74,49.53 212.09,49.53 212.09,45.72 206.76,45.72 197.49,36.45 197.49,19.69
CNTR_TAP_CHA on BOTTOM: 36.25,45.85 34.44,44.81 33.15,46.94 35,48.01
CNTR_TAP_CHB on BOTTOM: 29.9,58.39 29.9,55.78 32.03,55.78 32.03,58.39
CNTR_TAP_CHC on BOTTOM: 35.1,79.39 36.23,81.34 34.38,82.41 33.25,80.45
CNTR_TAP_CHD on BOTTOM: 32.06,68.61 29.94,68.59 30,70.97 32.16,70.99
RX_1.2V on TOP, BOTTOM: 112.9,34.92 112.9,33.25 118.41,33.25 118.41,34.92
RX_1.2V on BOTTOM: 57.1,59.69 57.1,61.26 64.97,61.26 65.33,61.62 65.33,65.47 65.04,65.76 57.1,65.76 57.1,67.28 66.24,67.28 67.08,66.45 67.08,60.6 66.17,59.69
RX_1.2V on L3_PWR: 113.03,33.1 113.03,48.89 105.33,56.59 64.95,56.59 61.98,59.56 57.07,59.56 57.07,60.96 57.25,61.14 106.71,61.14 118.49,49.35 118.49,33.1
RX_1.2V on L3_PWR: 61.72,66.04 61.72,67.44 57.4,67.44 56.9,67.94 56.9,72.14 54.66,72.14 54.66,67.64 56.26,66.04
RX_1.8V on TOP: 121.72,18.77 121.72,17.12 125.5,17.12 125.5,18.77
RX_1.8V on BOTTOM: 57.07,57 57.07,59.33 66.55,59.33 67.97,60.76 67.97,66.5 66.88,67.59 57.3,67.59 57.3,68.76 57.68,69.14 59.94,69.14 60.78,69.98 67.13,69.98 69.8,67.31 69.8,59.46 67.34,57
RX_1.8V on BOTTOM: 122.02,18.77 122.02,17.12 125.5,17.12 125.5,18.77
RX_1.8V on L3_PWR: 63.27,71.42 63.27,74.04 57.86,74.04 57.86,69.42 57.28,68.83 57.28,67.94 57.53,67.69 61.59,67.69
RX_1.8V on L3_PWR: 107.57,20.09 107.57,46.1 103.4,50.27 65.18,50.27 57.38,58.06 57.38,59.16 57.53,59.31 61.59,59.31 66.42,54.48 106.12,54.48 112.27,48.34 112.27,23.52 113.66,22.12 125.53,22.12 125.53,17.35 124.08,15.9 111.76,15.9
U16_SW on TOP: 152.48,20.78 152.48,13.11 153.34,13.11 153.34,11.56 150.6,11.56 150.6,20.78
VADJ on L3_PWR: 213.87,42.16 213.87,86.99 208.28,86.99 208.28,92.13 217.81,92.13 217.81,38.35 206.12,38.35 206.12,42.16
VIO_B_M2C on L3_PWR: 198.76,30.48 198.76,36.83 202.56,40.64 205.36,40.64 205.36,37.72 216.53,37.72 216.53,30.48
N17828171 on TOP: 195.33,94.45 195.33,91.4 198.28,91.4 198.28,94.45
N17828171 on BOTTOM: 195.31,93.41 195.31,91.4 198.3,91.4 198.3,93.41
N18332593 on TOP: 91.26,106.55 91.26,105.82 91.03,105.59 91.03,104.39 90.81,104.17 90.81,103.07 89.71,103.07 89.71,105.77 90.5,106.55
N18962088 on TOP: 179.22,33.66 179.22,31.22 184.38,31.22 184.38,33.66
N18962088 on BOTTOM: 180.64,35.26 180.64,33.15 181.84,31.95 184.28,31.95 184.28,33.32 182.35,35.26
N18963939 on TOP: 112.24,11.89 112.24,15.72 115.85,15.72 115.85,14.12 116.1,13.87 116.28,13.87 116.28,11.89
N18963939 on BOTTOM: 115.9,15.9 115.9,13.56 114.76,12.42 112.27,12.42 112.27,15.54 112.62,15.9
N18992183 on TOP: 126.01,24.84 126.01,28.88 129.46,28.88 129.46,26.87 129.92,26.87 129.92,25.73 129.46,25.73 129.46,24.84
N18992183 on BOTTOM: 129.46,28.93 129.46,25.73 126.01,25.73 126.01,28.93
N19007167 on TOP, BOTTOM: 148.34,1.27 148.34,8.15 153.29,8.15 153.29,3.63 164.08,3.63 164.08,1.27
N19010394 on TOP: 145.26,13.11 145.26,13.54 143.15,13.54 143.15,15.37 145.82,15.37 146.53,16.06 146.53,20.78 149.28,20.78 149.28,13.11
N19010394 on BOTTOM: 145.26,13.03 145.26,19.63 147.93,19.63 147.93,15.82 149.33,14.43 149.33,13.03
N19011541 on TOP: 137.34,13.54 137.34,15.95 138.35,15.95 138.35,20.27 139.75,20.27 140.39,19.63 145.34,19.63 145.34,17.6 142.8,17.6 142.42,17.22 142.42,13.54
N19011541 on BOTTOM: 137.34,13.54 137.34,16.08 137.46,15.95 138.35,15.95 138.35,19.63 142.42,19.63 142.42,13.54
N19083364 on L3_PWR: 98.32,96.34 98.32,85.67 101.98,85.67 101.98,96.34
N19083508 on TOP: 101.17,96.37 101.17,97.28 104.72,97.28 105.16,97.71 105.16,99.9 106.05,99.9 106.05,96.55 105.97,96.47 105.97,95.28 105.31,95.28 105.31,96.29 105.23,96.37
N20069572 on TOP: 80.14,12.83 80.14,8.89 81.79,8.89 81.79,12.83
N20070471 on TOP: 167.54,33.5 167.54,31.39 172.36,31.39 172.36,33.5
N20070471 on BOTTOM: 169.49,35.46 169.49,31.95 169.88,31.57 172.36,31.57 172.36,33.68 170.59,35.46
N20073169 on L8_PWR_SIG: 165.23,13.18 165.23,19.08 166.19,19.08 166.19,13.18
N20073179 on L8_PWR_SIG: 165.18,13 165.18,7.19 166.32,7.19 166.32,13
N20074438 on TOP: 143.41,28.88 143.41,32.84 147.04,32.84 147.04,30.91 147.47,30.91 147.47,29.85 147.04,29.85 147.04,28.88
N20074438 on BOTTOM: 147.04,32.82 147.04,29.82 143.41,29.82 143.41,32.82
N20081541 on TOP: 84.61,25.83 84.61,21.82 88.85,21.82 88.85,25.83
N20081541 on BOTTOM: 84.48,25.3 84.48,23.16 85.83,21.82 88.85,21.82 88.85,25.83 85.01,25.83
N20086075 on TOP: 123.65,8.76 123.65,12.75 127.3,12.75 127.3,11.1 127.66,10.74 127.66,9.8 126.06,9.8 126.06,8.76
N20086075 on BOTTOM: 123.65,9.83 123.65,12.88 127.28,12.88 127.28,9.83
N20090676 on TOP: 114.6,24.89 114.6,28.88 118.62,28.88 118.62,25.86 116.99,25.86 116.99,24.89
N20090676 on BOTTOM: 118.44,28.96 118.44,25.86 114.6,25.86 114.6,28.96

Small or netless copper shapes (teardrops, artwork), in the pictures only: 2 on L4_SIG

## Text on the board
BOTTOM: LAYER 10 (BOTTOM SIDE)
Board Geometry/Soldermask Bottom: SOLDERMASK BOTTOM
Ref Des/Silkscreen Bottom: SILKSCREEN BOTTOM
User.Comments: * | 6 | 10 | 5 | 1 | TP58 | U24 | U17 | TP59 | TP49 | TP47 | TP5 | TP64 | TP63 | TP2 | TP1 | ON | TP3 | 2 | 3 | TP4 | 4 | TP52 | TP51 | TP55 | TP50 | TP48 | TP33 | TP57 | TP13 | L | TP56 | TP53 | TP32 | TP34 | TP42 | 3.0V | TP62 | TP31 | TP35 | TP10 | L11 | 2.5V | A | TP36 | 1.8V | 11 | 1.4V | TP41 | TP60 | TP11 | TP12 | TP40 | TP37 | TP45 | TP43 | TP44 | TP38 | TP61 | TP39 | SW6 | TP54 | L13 | L4 | L14 | L5 | D1 | D2 | D3 | D4 | D5 | D6 | D7 | C136 | FB16 | C112 | D8 | D9 | JP5 | R149 | R151 | R150 | R139 | R147 | R146 | R144 | R142 | R143 | R145 | R141 | R148 | R121 | R156 | R109 | R136 | R130 | R125 | R128 | R115 | R124 | R152 | R157 | R154 | R112 | R110 | R120 | R114 | R133 | R332 | R333 | R359 | R360 | R308 | R105 | R309 | R155 | R117 | R127 | R113 | R129 | R122 | R111 | R153 | R118 | R137 | R132 | R126 | R135 | R123 | R108 | R106 | C474 | C472 | C486 | C488 | D22 | C228 | C226 | D11 | R119 | C254 | C255 | R217 | R218 | R192 | R204 | R191 | R203 | R190 | R202 | R563 | R564 | R189 | R201 | D13 | D14 | C422 | D15 | R488 | R489 | R491 | D17 | C426 | C431 | R482 | R481 | R490 | R492 | R234 | D19 | R236 | C266 | C267 | FB4 | FB3 | R235 | D18 | R468 | D16 | C465 | 9 | R474 | R467 | R472 | R475 | C482 | C433 | C483 | C434 | C443 | C444 | R8 | R11 | R14 | R16 | R18 | R19 | R20 | R24 | R100 | C537 | C534 | C535 | C536 | FB13 | FB14 | C479 | C477 | FB15 | C528 | R511 | C529 | R510 | C530 | C526 | C533 | C420 | C419 | R514 | C231 | R104 | VCCRT_1.03V | R213 | D10 | R216 | R212 | R226 | R230 | R214 | R206 | R484 | R194 | R485 | R221 | R199 | R227 | C425 | R187 | R231 | R200 | R188 | R219 | R205 | R220 | R228 | R193 | R232 | R209 | R197 | R208 | R238 | R196 | R243 | R207 | R195 | R247 | R244 | R473 | C408 | R239 | R245 | R470 | C402 | R513 | R515 | C469 | C470 | U18 | C435 | C440 | C436 | C441 | L6 | L7 | F1 | A1 | A4 | F4 | SW1 | SW7 | USB | RESET | SPARE | Q24 | Q20 | Q19 | Q18 | Q17 | Q16 | Q15 | Q14 | Q13 | Q12 | U28 | Q11 | Q10 | Q9 | RS2 | Q8 | Q7 | Q6 | U30 | Q5 | U26 | Q4 | Q3 | Q2 | Q1 | U19 | Y1 | J26 | U21 | J1 | J3 | FB12 | R215 | C279 | C274 | C296 | C297 | Y2 | FB17 | C306 | C285 | C277 | C275 | C286 | C276 | C287 | C292 | C294 | C293 | C295 | FB37 | C467 | C347 | R30 | R328 | C404 | C412 | R273 | R278 | R276 | R277 | C455 | C335 | C410 | C411 | C333 | C332 | C331 | C325 | C413 | C401 | C326 | R272 | R267 | C394 | C395 | R282 | C418 | C428 | C250 | C249 | C427 | C391 | C240 | C241 | C398 | C384 | C416 | C417 | R26 | C352 | R261 | C362 | R251 | R198 | R265 | R263 | C387 | C389 | C388 | C355 | C348 | C376 | C365 | C359 | C350 | R163 | C349 | C379 | C360 | C351 | C366 | R162 | T24 | R173 | R15 | R161 | R165 | R164 | R174 | C370 | C322 | C374 | C423 | C256 | C424 | C257 | C253 | R257 | R318 | R317 | R310 | R315 | R303 | R186 | R181 | R320 | R314 | R319 | R304 | R305 | R313 | R312 | R311 | R185 | R258 | R259 | R302 | C39 | C37 | C34 | C33 | C29 | C31 | C25 | C26 | C21 | C23 | C17 | C19 | C12 | C11 | C9 | C10 | R316 | R180 | C247 | R175 | R179 | C66 | C114 | C239 | C230 | C111 | R166 | C122 | C238 | C118 | C115 | C113 | C84 | C85 | C74 | C125 | C72 | C70 | C67 | C68 | C69 | C123 | C126 | C100 | C80 | C65 | C64 | C79 | C49 | C430 | C63 | C2 | C6 | C95 | C91 | R12 | R13 | C101 | T1 | R322 | R323 | C3 | T3 | C1 | C7 | R1 | T2 | C218 | C199 | R4 | C4 | C211 | C206 | R167 | R168 | C87 | C89 | C86 | C460 | C77 | C106 | C109 | C103 | C94 | C61 | L29 | C188 | C189 | C190 | C191 | C186 | C492 | C161 | B1 | E1 | G1 | H1 | K1 | C272 | C283 | C282 | C271 | C298 | C284 | C299 | C302 | C300 | C288 | C314 | C289 | R222 | R223 | R224 | R47 | C432 | R46 | R298 | R299 | R45 | R297 | R44 | R43 | R42 | R25 | C46 | R41 | R40 | C329 | C45 | C447 | R23 | R241 | C44 | R22 | C43 | C403 | R285 | R284 | C117 | R29 | C48 | R183 | R182 | R293 | R294 | R176 | R177 | R266 | R28 | C47 | R17 | C41 | C88 | R254 | R253 | R252 | R27 | C42 | C364 | R171 | C357 | R306 | R292 | R291 | R289 | R290 | C383 | C380 | C375 | R260 | R229 | C368 | C251 | C252 | R184 | C316 | C245 | R178 | C244 | C318 | L43 | C227 | L44 | C51 | C52 | C55 | C54 | C121 | C120 | R296 | C60 | C76 | C59 | R5 | C104 | C96 | C98 | C110 | R295 | C463 | C462 | L2 | R10 | R6 | L39 | L31 | C212 | R9 | C213 | R2 | C217 | C193 | C201 | C219 | C194 | C220 | C200 | C198 | A40 | B40 | C40 | D40 | E40 | F40 | G40 | H40 | J40 | K40 | C500 | C156 | A6 | A11 | A16 | A21 | A26 | A31 | A36 | K6 | K11 | K16 | K21 | K26 | K31 | K36 | C313 | C393 | C369 | C99 | C119 | C116 | C484 | C139 | C281 | C280 | C273 | C311 | C303 | C305 | R38 | R246 | R39 | R37 | R300 | R36 | C346 | C446 | R34 | R35 | R32 | R33 | R283 | R271 | R270 | C221 | C224 | R158 | R159 | R169 | C363 | R170 | R172 | C356 | C382 | C371 | C321 | C378 | C367 | C53 | C56 | C57 | C58 | R31 | C461 | L1 | R3 | R7 | C476 | C135 | C209 | C207 | C208 | L37 | C210 | C205 | C229 | C50 | C107 | C459 | C464 | C429 | C108 | C105 | C62 | C102 | C92 | C93 | C97 | C187 | C192 | VCCH_1.8V | VCCPT_1.8V | DDR_VDD_1.2V | TP46 | AP34 | GND | A34 | J12 | J15 | J13 | J14 | VADJ | 3.3V | 12V | AP1 | J17 | VCC_2.5V | DDR_2.5V | VCCIO_1.8V | VTTDDR_0.6V | USB_1.8V | USB INT# | VCC_.9V | VAR | USB_2.5V | USB_SP4 | SW7 (VAR) | U8 | U23 | OSC1 | USB_VDD_1.2V | REG_3.0V | U16 | U13 | CLKIN | CLKIN_32 | L3 | USB_VBATT | SW5 | U12 | U14 | SW2 | SW4 | 12 | 7 | U7 | L10 | U9 | J4 | 3.3V_UCD | R529 | C549 | R531 | C550 | R494 | C493 | R497 | R530 | R495 | R505 | R503 | R493 | R496 | C449 | A9 | T9 | R498 | C448 | R500 | C475 | FPGA JTAG | VCCIO | FPGA CONF | DONE | C397 | C458 | U6 | C442 | C466 | C450 | C452 | FB7 | FB9 | FB10 | PMODE0 | JP1 | R476 | U11 | JP2 | PMODE1 | D21 | JP4 | PMODE2 | PWR FAIL | J16 | J7 | M1 | M40 | L40 | Z40 | Z1 | Y40 | CN1 | CN2 | C491 | C490 | C489 | R534 | C437 | R533 | C494 | R501 | R502 | R499 | C551 | C386 | C73 | TX SYNC~ | C83 | TX CLK | RX SYNC~ | RX CLK | NOT USED | MEM INIT DONE~ | MEM SUCCESS~ | MEM PASS | FB11 | C456 | C457 | VCC_.09V | C399 | R478 | USB_VDD_1.2VV | FB8 | VTTDDR.6V | DDRVDD_1.2V | (8 PL) | ALPHANOVATECH # | PUSH PIN | 2 EA | NR35-25B-IP3N | TEXAS INSTRUMENTS | TSW14J57EVM REV B | SILKSCREEN TOP | Made in U.S.A. | +12V IN | TRIG_OUT_C | TRIG_OUT_B | TRIG_IN | TRIG_OUT_A | FAN PWR | UCD | POWER | CPU | SW3 | POWER RESET | PWR MON PC I/F | J2 | S/N | U1 | OFF | ADC/DAC FMC I/F | U2 | U3 | U4 | U5 | Pb | TXCLKOUT | AFECLK | J32 | LMK CLKIN | TEXAS INSTRUMENTS, INC. | PCB REV B | TSW14J57 | AFE74xxEVM  PCB REV D | TOP VIEW | BOTTOM VIEW
TOP: LAYER 1 (TOP SIDE)
Board Geometry/Soldermask Top: SOLDERMASK TOP
Ref Des/Silkscreen Top: STAT | ACCESS | J3 | J1 | J26 | TXCLKOUT | AFECLK | LMK CLKIN | 1.8V | EVM part number label | SERDES_1.5V | VDDR_ | S/N | SILKSCREEN TOP | DC017D
L2_GND: LAYER 2 - GND
L3_PWR: LAYER 3 - POWER
L4_SIG: LAYER 4 - SIGNAL
L5_GND: LAYER 5 - GROUND
L6_SIG: LAYER 6 - SIGNAL
L7_GND: LAYER 7 - GND
L8_PWR_SIG: LAYER 8 - POWER/SIGNAL
L9_GND: LAYER 9 - GROUND
PAGE_OUTLINE: DC017
DIMENSION: PASTEMASK TOP
DISPLAY_TOP: PASTEMASK BOTTOM
TOLERANCE_TOP: SOLDERMASK TOP SOCKET BOARD
USER_PART_NUM_TOP: PASTEMASK TOP SOCKET BOARD
User.11: R-5775K
User.12: 05-05-18 | 3. MARK BOARD'S SILKSCREEN AND ESD BAG WITH THE APPROPREATE EVM PART NUMBER. | 4. IPC-A-610 / ACCEPTABILITY OF ELECTRONIC ASSEMBLIES, CLASS 2, CURRENT REVISION. | 5. REFER TO HEATSINK DRAWING FOR REFERENCE OF HEATSINK HS1 ASSEMBLY. | DC017
User.16: FIGURE | SIZE | 6.0 | 8.0 | 10.0 | 12.0 | 15.0 | 38.0 | 40.0 | 46.0 | 55.0 | 62.0 | 106.0 | 120.0 | 125.0 | 140.0 | 35.43 | 50.0 | DRILL CHART: TOP to BOTTOM | ALL UNITS ARE IN MILS | PLATED | NON-PLATED | QTY | 242 | 25 | 36 | 5362 | 417 | 995 | 72 | 223 | 3 | 28 | 2 | 8 | 1
